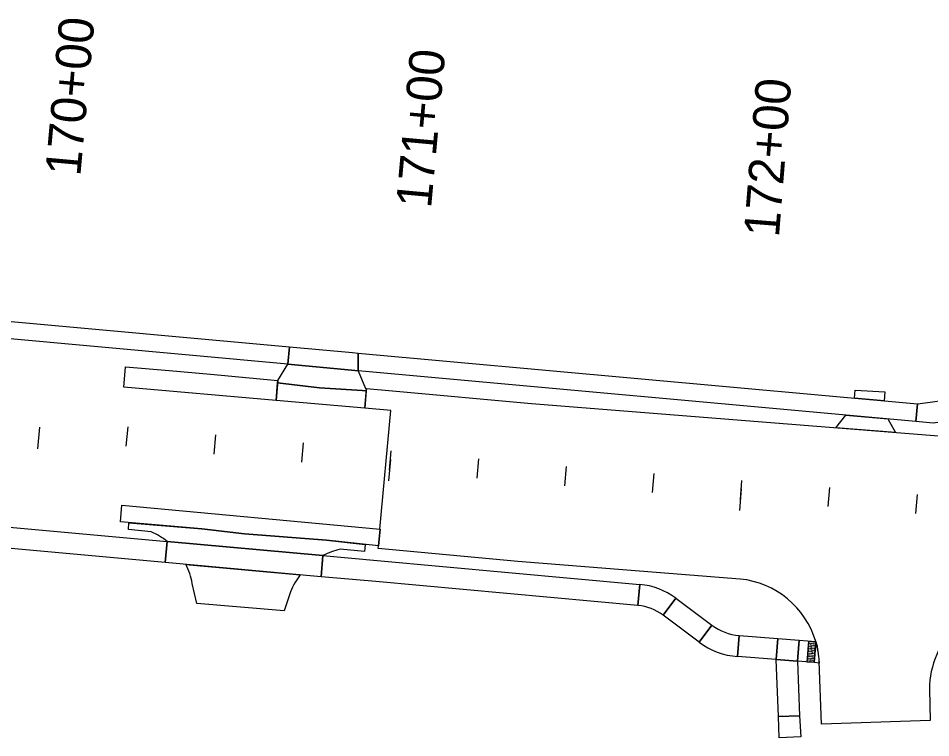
# Model space of a CAD drawing. Extents: x 20499216 to 20505321, y 7953487 to 7960535.
# Drawn here: x 20500706.4 to 20500965.4, y 7953896.4 to 7954100.9 of the extents above; entities that cross this region are included whole.
import ezdxf

# ---------------------------------------------------------------- set-up
doc = ezdxf.new("R2010")
doc.units = 0
for name, color, linetype in [('Drainage', 7, 'Continuous'), ('EXT_CU', 7, 'Continuous'), ('EXT_RR', 7, 'Continuous'), ('NamedBoundary', 7, 'Continuous'), ('Roadways', 7, 'Continuous'), ('Safety', 7, 'Continuous')]:
    doc.layers.add(name, color=color, linetype=linetype)

msp = doc.modelspace()

# ---------------------------------------------------------------- linework, layer by layer
at = {"layer": 'Drainage'}
for p, q in [((20500899.68, 7953923.6), (20500903.27, 7953928.41)), ((20500911.07, 7953925.46), (20500910.6, 7953919.48))]:
    msp.add_line(p, q, dxfattribs=at)
for points in [[(20500899.68, 7953923.6), (20500889.43, 7953931.27), (20500893.03, 7953936.07), (20500903.27, 7953928.41)], [(20500921.59, 7953918.61), (20500910.6, 7953919.48), (20500911.07, 7953925.46), (20500922.06, 7953924.59), (20500921.59, 7953918.61)], [(20500932.3, 7953917.75), (20500927.61, 7953918.13), (20500928.08, 7953924.11), (20500932.78, 7953923.74), (20500932.78, 7953923.74), (20500932.3, 7953917.75)]]:
    msp.add_lwpolyline(points, close=True, dxfattribs=at)
msp.add_lwpolyline([(20500933.77, 7953918.06), (20500933.79, 7953917.64), (20500932.3, 7953917.75), (20500932.78, 7953923.74)], dxfattribs=at)
for centre, radius, start, end in [((20500912.26, 7953940.41), 15, 233.1801, 265.4563), ((20500912.26, 7953940.41), 21, 233.1801, 265.4563), ((20500908.31, 7953916.52), 25.51, 3.4563, 16.432)]:
    msp.add_arc(centre, radius, start, end, dxfattribs=at)
at = {"layer": 'EXT_CU'}
for p, q in [((20500930.31, 7953917.91), (20500930.78, 7953923.89)), ((20500930.78, 7953923.89), (20500932.78, 7953923.74)), ((20500932.78, 7953923.74), (20500932.3, 7953917.75)), ((20500932.3, 7953917.75), (20500930.31, 7953917.91))]:
    msp.add_line(p, q, dxfattribs=at)
for points in [[(20500700.89, 7954010.01), (20500701.21, 7954015), (20500783.37, 7954007.51), (20500782.92, 7954002.53)], [(20500965.3, 7953991.78), (20501114.4, 7954012.75), (20501316.65, 7953998.09), (20501476.2, 7953950.79), (20501496.14, 7953949.21), (20501511.25, 7953950.02), (20501604.78, 7953942.58), (20501718.78, 7953932.38), (20501718.33, 7953927.4), (20501604.36, 7953937.6), (20501511.18, 7953945), (20501496.07, 7953944.2), (20501475.28, 7953945.85), (20501320.22, 7953991.82), (20501114.61, 7954006.72), (20500966.14, 7953985.84), (20500961.2, 7953986.29), (20500961.66, 7953991.27)], [(20500801, 7954000.88), (20500782.92, 7954002.53), (20500783.37, 7954007.51), (20500801.23, 7954005.88), (20500802.86, 7954005.74), (20500802.85, 7954000.72)], [(20500802.86, 7954005.74), (20500961.66, 7953991.27), (20500961.2, 7953986.29), (20500802.85, 7954000.72)], [(20500943.78, 7953992.9), (20500943.99, 7953995.2), (20500952.43, 7953994.73), (20500952.19, 7953992.13), (20500943.78, 7953992.9)], [(20500655.34, 7953954.63), (20500655.89, 7953960.61), (20500748.67, 7953952.18), (20500748.12, 7953946.2)], [(20500748.12, 7953946.2), (20500748.67, 7953952.18), (20500792.88, 7953948.16), (20500792.34, 7953942.18)], [(20500808.25, 7953946.76), (20500882.85, 7953939.98), (20500882.31, 7953934.01), (20500807.92, 7953940.85), (20500792.34, 7953942.18), (20500792.88, 7953948.16)], [(20500928.19, 7953902.64), (20500922.19, 7953902.42), (20500921.59, 7953918.61), (20500927.61, 7953918.13)], [(20500922.42, 7953896.4), (20500922.19, 7953902.42), (20500928.19, 7953902.64), (20500928.56, 7953896.65)]]:
    msp.add_lwpolyline(points, close=True, dxfattribs=at)
for centre, major_axis in [((20500930.95, 7953923.24), (-0.0037, -0.0448)), ((20500930.95, 7953923.24), (-0.0019, -0.0224)), ((20500930.99, 7953923.71), (-0.0037, -0.0448)), ((20500930.99, 7953923.71), (-0.0019, -0.0224)), ((20500931.35, 7953923.21), (-0.0037, -0.0448)), ((20500931.35, 7953923.21), (-0.0019, -0.0224)), ((20500931.38, 7953923.68), (-0.0037, -0.0448)), ((20500931.38, 7953923.68), (-0.0019, -0.0224)), ((20500931.74, 7953923.18), (-0.0037, -0.0448)), ((20500931.77, 7953923.64), (-0.0037, -0.0448)), ((20500931.77, 7953923.64), (-0.0019, -0.0224)), ((20500932.16, 7953923.61), (-0.0037, -0.0448)), ((20500932.16, 7953923.61), (-0.0019, -0.0224)), ((20500932.55, 7953923.58), (-0.0037, -0.0448)), ((20500932.55, 7953923.58), (-0.0019, -0.0224)), ((20500930.77, 7953920.9), (-0.0037, -0.0448)), ((20500930.77, 7953920.9), (-0.0019, -0.0224)), ((20500930.8, 7953921.36), (-0.0037, -0.0448)), ((20500930.8, 7953921.36), (-0.0019, -0.0224)), ((20500930.84, 7953921.83), (-0.0037, -0.0448)), ((20500930.84, 7953921.83), (-0.0019, -0.0224)), ((20500930.88, 7953922.3), (-0.0037, -0.0448)), ((20500930.88, 7953922.3), (-0.0019, -0.0224)), ((20500930.92, 7953922.77), (-0.0037, -0.0448)), ((20500930.92, 7953922.77), (-0.0019, -0.0224)), ((20500931.16, 7953920.86), (-0.0037, -0.0448)), ((20500931.16, 7953920.86), (-0.0019, -0.0224)), ((20500931.19, 7953921.33), (-0.0037, -0.0448)), ((20500931.19, 7953921.33), (-0.0019, -0.0224)), ((20500931.23, 7953921.8), (-0.0037, -0.0448)), ((20500931.23, 7953921.8), (-0.0019, -0.0224)), ((20500931.27, 7953922.27), (-0.0037, -0.0448)), ((20500931.27, 7953922.27), (-0.0019, -0.0224)), ((20500931.31, 7953922.74), (-0.0037, -0.0448)), ((20500931.31, 7953922.74), (-0.0019, -0.0224)), ((20500931.55, 7953920.83), (-0.0037, -0.0448)), ((20500931.55, 7953920.83), (-0.0019, -0.0224)), ((20500931.59, 7953921.3), (-0.0037, -0.0448)), ((20500931.59, 7953921.3), (-0.0019, -0.0224)), ((20500931.62, 7953921.77), (-0.0037, -0.0448)), ((20500931.62, 7953921.77), (-0.0019, -0.0224)), ((20500931.66, 7953922.24), (-0.0037, -0.0448)), ((20500931.66, 7953922.24), (-0.0019, -0.0224)), ((20500931.7, 7953922.71), (-0.0037, -0.0448)), ((20500931.7, 7953922.71), (-0.0019, -0.0224)), ((20500931.74, 7953923.18), (-0.0019, -0.0224)), ((20500931.94, 7953920.8), (-0.0037, -0.0448)), ((20500931.94, 7953920.8), (-0.0019, -0.0224)), ((20500931.98, 7953921.27), (-0.0037, -0.0448)), ((20500931.98, 7953921.27), (-0.0019, -0.0224)), ((20500932.01, 7953921.74), (-0.0037, -0.0448)), ((20500932.01, 7953921.74), (-0.0019, -0.0224)), ((20500932.05, 7953922.21), (-0.0037, -0.0448)), ((20500932.05, 7953922.21), (-0.0019, -0.0224)), ((20500932.09, 7953922.68), (-0.0037, -0.0448)), ((20500932.09, 7953922.68), (-0.0019, -0.0224)), ((20500932.13, 7953923.15), (-0.0037, -0.0448)), ((20500932.13, 7953923.15), (-0.0019, -0.0224)), ((20500932.33, 7953920.77), (-0.0037, -0.0448)), ((20500932.33, 7953920.77), (-0.0019, -0.0224)), ((20500932.37, 7953921.24), (-0.0037, -0.0448)), ((20500932.37, 7953921.24), (-0.0019, -0.0224)), ((20500932.4, 7953921.71), (-0.0037, -0.0448)), ((20500932.4, 7953921.71), (-0.0019, -0.0224)), ((20500932.44, 7953922.18), (-0.0037, -0.0448)), ((20500932.44, 7953922.18), (-0.0019, -0.0224)), ((20500932.48, 7953922.65), (-0.0037, -0.0448)), ((20500932.48, 7953922.65), (-0.0019, -0.0224)), ((20500932.52, 7953923.11), (-0.0037, -0.0448)), ((20500932.52, 7953923.11), (-0.0019, -0.0224)), ((20500930.54, 7953918.06), (-0.0037, -0.0448)), ((20500930.54, 7953918.06), (-0.0019, -0.0224)), ((20500930.58, 7953918.53), (-0.0037, -0.0448)), ((20500930.58, 7953918.53), (-0.0019, -0.0224)), ((20500930.61, 7953919), (-0.0037, -0.0448)), ((20500930.61, 7953919), (-0.0019, -0.0224)), ((20500930.65, 7953919.49), (-0.0037, -0.0448)), ((20500930.65, 7953919.49), (-0.0019, -0.0224)), ((20500930.69, 7953919.96), (-0.0037, -0.0448)), ((20500930.69, 7953919.96), (-0.0019, -0.0224)), ((20500930.73, 7953920.43), (-0.0037, -0.0448)), ((20500930.73, 7953920.43), (-0.0019, -0.0224)), ((20500930.93, 7953918.03), (-0.0037, -0.0448)), ((20500930.93, 7953918.03), (-0.0019, -0.0224)), ((20500930.97, 7953918.5), (-0.0037, -0.0448)), ((20500930.97, 7953918.5), (-0.0019, -0.0224)), ((20500931.01, 7953918.97), (-0.0037, -0.0448)), ((20500931.01, 7953918.97), (-0.0019, -0.0224)), ((20500931.04, 7953919.46), (-0.0037, -0.0448)), ((20500931.04, 7953919.46), (-0.0019, -0.0224)), ((20500931.08, 7953919.93), (-0.0037, -0.0448)), ((20500931.08, 7953919.93), (-0.0019, -0.0224)), ((20500931.12, 7953920.4), (-0.0037, -0.0448)), ((20500931.12, 7953920.4), (-0.0019, -0.0224)), ((20500931.32, 7953918), (-0.0037, -0.0448)), ((20500931.36, 7953918.47), (-0.0037, -0.0448)), ((20500931.36, 7953918.47), (-0.0019, -0.0224)), ((20500931.4, 7953918.94), (-0.0037, -0.0448)), ((20500931.4, 7953918.94), (-0.0019, -0.0224)), ((20500931.44, 7953919.43), (-0.0037, -0.0448)), ((20500931.44, 7953919.43), (-0.0019, -0.0224)), ((20500931.47, 7953919.9), (-0.0037, -0.0448)), ((20500931.47, 7953919.9), (-0.0019, -0.0224)), ((20500931.51, 7953920.37), (-0.0037, -0.0448)), ((20500931.51, 7953920.37), (-0.0019, -0.0224)), ((20500931.75, 7953918.44), (-0.0037, -0.0448)), ((20500931.75, 7953918.44), (-0.0019, -0.0224)), ((20500931.79, 7953918.9), (-0.0037, -0.0448)), ((20500931.79, 7953918.9), (-0.0019, -0.0224)), ((20500931.83, 7953919.4), (-0.0037, -0.0448)), ((20500931.83, 7953919.4), (-0.0019, -0.0224)), ((20500931.86, 7953919.87), (-0.0037, -0.0448)), ((20500931.86, 7953919.87), (-0.0019, -0.0224)), ((20500931.9, 7953920.33), (-0.0037, -0.0448)), ((20500931.9, 7953920.33), (-0.0019, -0.0224)), ((20500932.14, 7953918.41), (-0.0037, -0.0448)), ((20500932.14, 7953918.41), (-0.0019, -0.0224)), ((20500932.18, 7953918.87), (-0.0037, -0.0448)), ((20500932.18, 7953918.87), (-0.0019, -0.0224)), ((20500932.22, 7953919.37), (-0.0037, -0.0448)), ((20500932.22, 7953919.37), (-0.0019, -0.0224)), ((20500932.25, 7953919.84), (-0.0037, -0.0448)), ((20500932.25, 7953919.84), (-0.0019, -0.0224)), ((20500932.29, 7953920.3), (-0.0037, -0.0448)), ((20500932.29, 7953920.3), (-0.0019, -0.0224)), ((20500931.32, 7953918), (-0.0019, -0.0224)), ((20500931.71, 7953917.97), (-0.0037, -0.0448)), ((20500931.71, 7953917.97), (-0.0019, -0.0224)), ((20500932.1, 7953917.94), (-0.0037, -0.0448)), ((20500932.1, 7953917.94), (-0.0019, -0.0224))]:
    msp.add_ellipse(centre, major_axis=major_axis, ratio=0.833333, dxfattribs=at)
at = {"layer": 'EXT_RR'}
for p, q in [((20500712.43, 7953984.62), (20500711.88, 7953978.53)), ((20500737.05, 7953979.29), (20500737.55, 7953984.73)), ((20500761.95, 7953977.02), (20500762.44, 7953982.45)), ((20500786.84, 7953974.74), (20500787.34, 7953980.18)), ((20500812.02, 7953975.51), (20500811.46, 7953969.41)), ((20500836.64, 7953970.18), (20500837.13, 7953975.62)), ((20500861.54, 7953968.04), (20500861.98, 7953973.48)), ((20500886.46, 7953966.06), (20500886.9, 7953971.5)), ((20500936.31, 7953962.1), (20500936.74, 7953967.54)), ((20500911.63, 7953967.13), (20500911.14, 7953961.03)), ((20500961.23, 7953960.12), (20500961.66, 7953965.56))]:
    msp.add_line(p, q, dxfattribs=at)
at = {"layer": 'NamedBoundary'}
for p, q in [((20500792.88, 7953948.16), (20500748.67, 7953952.18)), ((20500753.95, 7953945.67), (20500786.43, 7953942.72))]:
    msp.add_line(p, q, dxfattribs=at)
for points in [[(20500779.58, 7953992.26), (20500736.34, 7953996.01), (20500736.84, 7954001.82), (20500749.26, 7954000.78), (20500760.93, 7953999.71), (20500780.08, 7953997.97)], [(20500802.92, 7954000.71), (20500804.94, 7953995.65), (20500805.25, 7953995.63), (20500805.19, 7953994.96), (20500804.89, 7953994.98), (20500803.97, 7953995.06), (20500791.89, 7953995.84), (20500780.02, 7953997.3), (20500780.08, 7953997.97), (20500782.92, 7954002.53), (20500801, 7954000.88), (20500802.92, 7954000.71)], [(20500804.8, 7953990.06), (20500779.58, 7953992.26), (20500780.02, 7953997.3), (20500791.89, 7953995.84), (20500803.97, 7953995.06), (20500805.19, 7953994.96)], [(20500938.49, 7953984.5), (20500941.37, 7953988.1), (20500953.26, 7953987.01), (20500955.44, 7953983.15)], [(20500809.17, 7953955.67), (20500808.63, 7953950.91), (20500793.87, 7953952.59), (20500770.59, 7953954.37), (20500758.5, 7953955.73), (20500735.36, 7953957.73), (20500735.77, 7953962.48)]]:
    msp.add_lwpolyline(points, close=True, dxfattribs=at)
for points in [[(20500911.34, 7953941.51), (20500848.24, 7953946.53), (20500808.56, 7953950.16), (20500808.63, 7953950.91), (20500808.63, 7953950.91), (20500809.17, 7953955.67), (20500809.06, 7953955.68), (20500812.15, 7953989.44), (20500804.8, 7953990.07), (20500805.25, 7953995.63), (20500812.66, 7953994.97), (20500852.08, 7953991.36), (20501603.86, 7953931.62), (20501734.26, 7953919.95)], [(20500744.1, 7953954.94), (20500737.64, 7953955.54), (20500737.81, 7953957.51), (20500758.5, 7953955.73), (20500770.59, 7953954.37), (20500793.87, 7953952.59), (20500804.87, 7953951.34), (20500804.7, 7953949.35), (20500797.78, 7953949.99)], [(20500783.68, 7953937.9), (20500781.85, 7953932.48), (20500757.09, 7953934.51), (20500755.78, 7953940.28)], [(20500932.78, 7953923.72), (20500932.78, 7953923.74), (20500932.78, 7953923.74)], [(20500965.07, 7953910.21), (20500965.3, 7953901.35), (20500934.39, 7953900.27), (20500933.77, 7953918.06)]]:
    msp.add_lwpolyline(points, dxfattribs=at)
for centre, radius, start, end in [((20500736.12, 7953936.6), 20, 51.1592, 66.4896), ((20500802.26, 7953930.49), 20, 102.9322, 117.9663), ((20500736.12, 7953936.6), 20, 10.6171, 26.9786), ((20500802.26, 7953930.49), 20, 142.3169, 158.2767), ((20500908.79, 7953916.62), 25.02, 16.515, 84.1449), ((20500990.1, 7953910.15), 25.03, 87.0999, 179.8665), ((20500908.16, 7953916.49), 25.66, 3.4965, 16.3696), ((20500909.41, 7953917.21), 24.38, 1.9853, 15.4702)]:
    msp.add_arc(centre, radius, start, end, dxfattribs=at)
at = {"layer": 'Roadways'}
for p, q in [((20500882.31, 7953934.01), (20500882.85, 7953939.98)), ((20500893.03, 7953936.07), (20500889.43, 7953931.27))]:
    msp.add_line(p, q, dxfattribs=at)
msp.add_lwpolyline([(20500927.61, 7953918.13), (20500921.59, 7953918.61), (20500922.06, 7953924.59), (20500928.08, 7953924.11), (20500928.08, 7953924.11), (20500927.61, 7953918.13)], close=True, dxfattribs=at)
for radius in [20, 14]:
    msp.add_arc((20500881.04, 7953920.06), radius, 53.1801, 84.8067, dxfattribs=at)
at = {"layer": 'Safety'}
for p, q in [((20500712.43, 7953984.62), (20500711.88, 7953978.53)), ((20500811.74, 7953972.46), (20500812.24, 7953977.9)), ((20500911.39, 7953964.08), (20500911.82, 7953969.52))]:
    msp.add_line(p, q, dxfattribs=at)

# ---------------------------------------------------------------- texts
at = {"layer": 'EXT_RR'}
for s, rotation, p in [('170+00', 84.7714, (20500723.98, 7954055.8)), ('171+00', 84.7714, (20500823.56, 7954046.69)), ('172+00', 85.4564, (20500922.32, 7954038.45))]:
    msp.add_text(s, height=10.02, rotation=rotation, dxfattribs=at).set_placement(p)
at = {"layer": 'Safety'}
msp.add_text('170+00', height=10.02, rotation=84.7714, dxfattribs=at).set_placement((20500723.98, 7954055.8))

doc.saveas('drawing.dxf')
